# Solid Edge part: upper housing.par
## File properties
Author: Robert a Rhodes jr
Template: NORMENG.PAR
Last saved by: CADCIM
Revision: 9
Application: Solid Edge
Density: 0 lbm/in^3
Accuracy: 0.99
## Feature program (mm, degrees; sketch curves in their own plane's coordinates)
sketch for "unnamed Protrusion 1" plane through (0, 0, 0) normal (0, -1, 0) x-axis (1, 0, 0)
  arc centre (0, 0) radius 152.4 from (152.4, 0) to (-152.4, 0) ccw
  line (-152.4, 0) -> (152.4, 0)
extrude "unnamed Protrusion 1" add finite 203.2 symmetric
swept protrusion "SweptProtrusion_1"  Profile_5_Plane_FractionOfCurve = 0
fillet "Round_1" radius 38.1
fillet "Round_2" radius 12.7
thinwall "Thinwall_2"  Thickness = 6.35 mm
sketch for "unnamed Cutout 1" plane through (0, -101.6, 76.2) normal (0, -1, 0) x-axis (1, 0, 0)
  arc centre (0, -76.2) radius 123.825 from (-123.825, -76.2) to (123.825, -76.2) cw
extrude "unnamed Cutout 1" cut through along -normal
sketch for "unnamed Cutout 2" plane through (0, 95.25, 73.025) normal (0, -1, 0) x-axis (1, 0, 0)
  arc centre (0, -73.025) radius 38.1 from (38.1, -73.025) to (-38.1, -73.025) ccw
extrude "unnamed Cutout 2" cut through along -normal
sketch for "ExtrudedProtrusion_2" plane through (0, -101.6, 76.2) normal (0, -1, 0) x-axis (1, 0, 0)
  line (152.4, -76.2) -> (190.5, -76.2)
  line (190.5, -76.2) -> (190.5, -66.04)
  line (190.5, -66.04) -> (152.061, -66.04)
  arc centre (0, -76.2) radius 152.4 from (152.4, -76.2) to (152.061, -66.04) ccw
extrude "ExtrudedProtrusion_2" add finite 203.2 along -normal
mirror "unnamed Mirror 1" of "ExtrudedProtrusion_2" about plane through (0, 0, 0) normal (1, 0, 0)
extrude "unnamed Protrusion 2" add finite 203.2
sketch for "Hole_1" plane through (171.2507, 0, 10.16) normal (0, 0, 1) x-axis (0, 1, 0)
hole "Hole_1" diameter 10.414 through
pattern "unnamed Pattern 1" of "Hole_1"
pattern "unnamed Pattern 2"
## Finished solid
Body 1: solid body, 69 faces, 164 edges, 88 vertices.
  Faces by surface: blend 24, plane 15, cylinder 14, offset 6, spline 6, torus 4
  Edges by curve: circle 60, intersection 56, line 45, curve on surface 3
Bounding box of the edges (mm; curved faces can reach further): 492.760 x 203.200 x 255.273, from (-302.26, -101.6, 0) to (190.5, 101.6, 255.2731).
Cylindrical faces by radius (mm): R5.207 x8, R12.7 x1, R19.05 x1, R38.1 x1, R123.825 x1, R146.05 x1, R152.4 x1
Toroidal faces (ring radius, tube radius in mm): R165.1 r12.7 x2, R165.1 r19.05 x2
Planar faces by outward normal: +x 1, +y 4, +z 2, -x 2, -y 4, -z 2
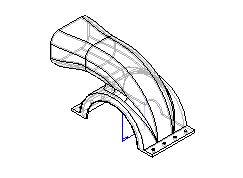
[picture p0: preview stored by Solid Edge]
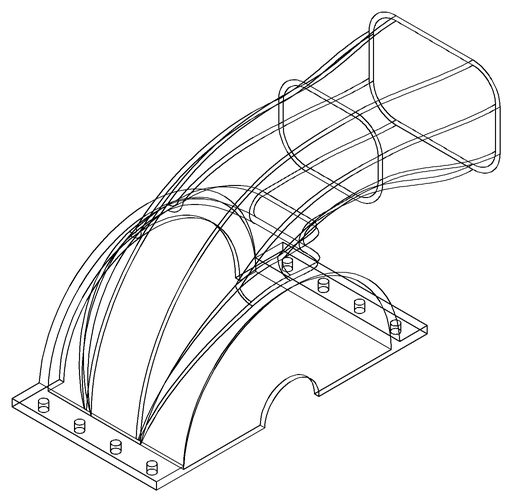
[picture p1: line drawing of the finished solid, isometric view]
